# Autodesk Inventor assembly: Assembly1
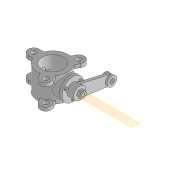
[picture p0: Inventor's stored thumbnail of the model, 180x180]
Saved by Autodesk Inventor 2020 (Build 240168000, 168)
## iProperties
Created: 2019-03
Part Number: Assembly1
Document SubType Name: Assembly
Designer: LENOVO-CADCIM
Author: LENOVO-CADCIM
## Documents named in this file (10)
- D:\Autodesk Inventor_2020\Resources1\c09\Butterfly Valve\Assembly1.iam
- D:\Autodesk Inventor_2020\Resources1\c09\Butterfly Valve\Body.ipt
- D:\Autodesk Inventor_2020\Resources1\c09\Butterfly Valve\Shaft.ipt
- D:\Autodesk Inventor_2020\Resources1\c09\Butterfly Valve\Retainer.ipt
- D:\Autodesk Inventor_2020\Resources1\c09\Butterfly Valve\Arm1.ipt
- D:\Autodesk Inventor_2020\Resources1\c09\Butterfly Valve\Plate.ipt
- D:\Autodesk Inventor_2020\Resources1\c09\Butterfly Valve\scew1.ipt
- D:\Autodesk Inventor_2020\Resources1\c09\Butterfly Valve\Screw.ipt
- D:\Autodesk Inventor_2020\Resources1\c09\Butterfly Valve\Parallel key.ipt
- D:\Autodesk Inventor_2020\Resources1\c09\Butterfly Valve\Nut.ipt
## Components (12 placed, 9 different names)
1. Body:1 — Insert:1, Insert:2, Mate:1, Angle:4, Angle:5
2. Shaft:1 — Insert:1, Insert:3, Insert:4, Mate:3, Insert:11, Angle:5
3. Retainer:1 — Insert:2, Mate:1, Insert:7, Insert:8, Insert:9, Insert:10
4. Arm1:1 — Insert:10, Mate:2, Flush:1
5. Plate:1 — Insert:3, Insert:4, Insert:5, Insert:6
6. scew1:1 — Insert:5
7. scew1:2 — Insert:6
8. Screw:1 — Insert:7
9. Screw:2 — Insert:8
10. Screw:3 — Insert:9
11. Parallel key:1 — Mate:2, Mate:3, Flush:1
12. Nut:1 — Insert:11, Angle:4
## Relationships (17: Insert 11, Mate 3, Angle 2, Flush 1)
- Insert:1: Body:1 ↔ Shaft:1
- Insert:2: Body:1 ↔ Retainer:1
- Mate:1: Body:1 ↔ Retainer:1
- Insert:3: Shaft:1 ↔ Plate:1
- Insert:4: Shaft:1 ↔ Plate:1
- Insert:5: Plate:1 ↔ scew1:1
- Insert:6: Plate:1 ↔ scew1:2
- Insert:7: Retainer:1 ↔ Screw:1
- Insert:8: Retainer:1 ↔ Screw:2
- Insert:9: Retainer:1 ↔ Screw:3
- Insert:10: Retainer:1 ↔ Arm1:1
- Mate:2: Arm1:1 ↔ Parallel key:1
- Mate:3: Shaft:1 ↔ Parallel key:1
- Flush:1: Arm1:1 ↔ Parallel key:1
- Insert:11: Shaft:1 ↔ Nut:1
- Angle:4: Body:1 ↔ Nut:1
- Angle:5: Body:1 ↔ Shaft:1
